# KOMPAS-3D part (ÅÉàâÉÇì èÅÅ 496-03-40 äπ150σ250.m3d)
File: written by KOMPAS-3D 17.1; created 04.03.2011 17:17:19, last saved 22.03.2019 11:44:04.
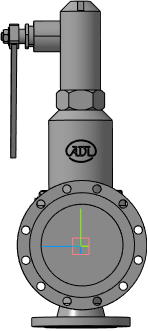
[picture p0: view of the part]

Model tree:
1. Плоскость XY
2. Плоскость ZX
3. Плоскость ZY
4. Ось X
5. Ось Y
6. Ось Z
7. Начало координат
8. Операция без истории:3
